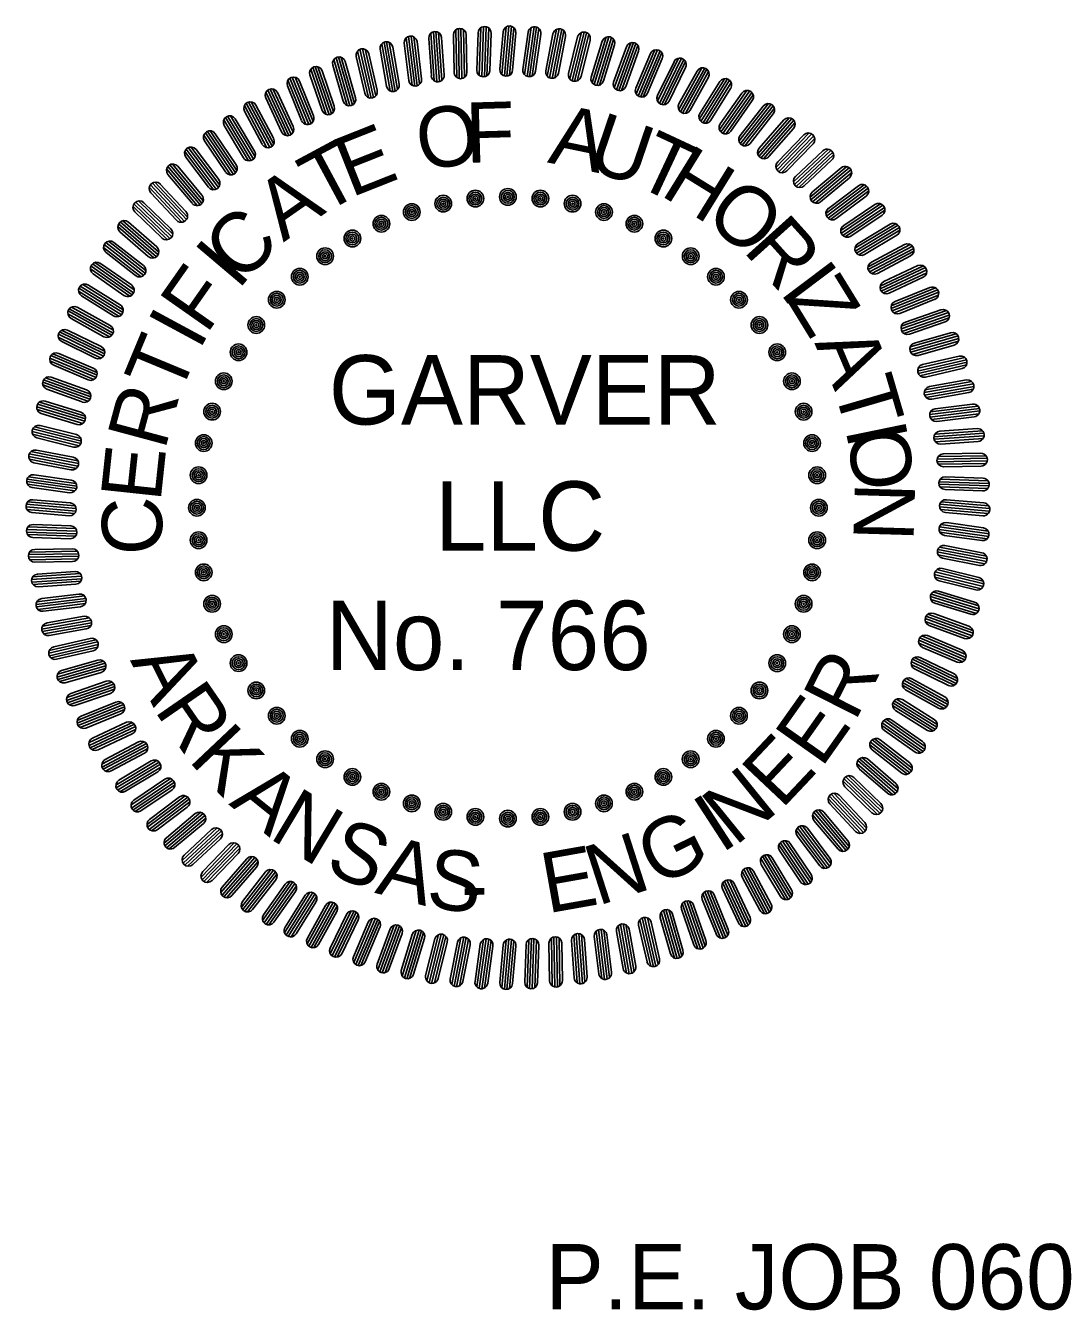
# Model space of a CAD drawing. Extents: x 1373884 to 1377798, y 1168424 to 1170626.
# Drawn here: x 1377288.9 to 1377543.4, y 1168462.5 to 1168777.3 of the extents above; entities that cross this region are included whole.
import ezdxf

# ---------------------------------------------------------------- set-up
doc = ezdxf.new("R2010")
doc.units = 0
doc.layers.add('2', color=7, linetype='Continuous')
doc.layers.add('G-ANNO-TEXT', color=7, linetype='Continuous')

# ---------------------------------------------------------------- blocks, each defined once
blk = doc.blocks.new('SEALDO')
at = {"layer": 'G-ANNO-TEXT'}
for radius in [0.0396, 0.0305, 0.0213, 0.0122, 0.00305]:
    blk.add_circle((1.403, -0.4559), radius, dxfattribs=at)
blk = doc.blocks.new('SEALRI')
at = {"layer": 'G-ANNO-TEXT'}
for p, q in [((-0.0226, 2.2583), (-0.0381, 2.0809)), ((-0.0083, 2.2815), (-0.0281, 2.0555)), ((0.0043, 2.2859), (-0.0164, 2.049)), ((0.0164, 2.2848), (-0.0043, 2.0479)), ((0.0281, 2.2783), (0.0083, 2.0523)), ((0.0226, 2.0756), (0.0381, 2.253))]:
    blk.add_line(p, q, dxfattribs=at)
for centre, start, end in [((0.0078, 2.2556), 355, 175), ((-0.0078, 2.0782), 175, 355)]:
    blk.add_arc(centre, 0.0305, start, end, dxfattribs=at)

msp = doc.modelspace()

# ---------------------------------------------------------------- block references
at = {"layer": 'G-ANNO-TEXT'}
for name, xscale, yscale, rotation in [('SEALRI', 51.64309671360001, 51.643096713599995, 3.0000000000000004), ('SEALRI', 51.64309671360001, 51.6430967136, -2.999999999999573), ('SEALRI', 51.643096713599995, 51.64309671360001, 15.000000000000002), ('SEALRI', 51.643096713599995, 51.643096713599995, 12), ('SEALRI', 51.64309671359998, 51.64309671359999, 9.000000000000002), ('SEALRI', 51.6430967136, 51.643096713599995, 6.000000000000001), ('SEALRI', 51.6430967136, 51.643096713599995, -5.99999999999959), ('SEALRI', 51.643096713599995, 51.64309671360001, -8.999999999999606), ('SEALRI', 51.64309671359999, 51.64309671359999, -11.999999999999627), ('SEALRI', 51.6430967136, 51.64309671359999, -14.99999999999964), ('SEALRI', 51.64309671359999, 51.64309671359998, 18.000000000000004), ('SEALRI', 51.643096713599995, 51.643096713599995, -17.999999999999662), ('SEALRI', 51.6430967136, 51.643096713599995, 23.99999999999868), ('SEALRI', 51.6430967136, 51.643096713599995, 20.99999999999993), ('SEALRI', 51.64309671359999, 51.64309671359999, -20.999999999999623), ('SEALRI', 51.643096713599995, 51.6430967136, -23.999999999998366), ('SEALRI', 51.6430967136, 51.643096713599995, 26.999999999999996), ('SEALRI', 51.643096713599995, 51.643096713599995, -26.99999999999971), ('SEALRI', 51.6430967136, 51.64309671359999, 30.000000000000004), ('SEALRI', 51.64309671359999, 51.6430967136, -29.999999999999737), ('SEALRI', 51.643096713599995, 51.64309671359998, 33), ('SEALRI', 51.6430967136, 51.6430967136, -32.999999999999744), ('SEALRI', 51.643096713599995, 51.64309671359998, 36), ('SEALRI', 51.643096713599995, 51.643096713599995, -35.999999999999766), ('SEALRI', 51.6430967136, 51.6430967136, 38.999999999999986), ('SEALRI', 51.64309671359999, 51.64309671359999, -38.99999999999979), ('SEALRI', 51.64309671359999, 51.64309671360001, 41.99999999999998), ('SEALRI', 51.6430967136, 51.643096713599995, -41.99999999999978), ('SEALRI', 51.643096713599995, 51.64309671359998, 44.999999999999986), ('SEALRI', 51.6430967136, 51.6430967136, -44.99999999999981), ('SEALRI', 51.643096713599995, 51.6430967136, 48), ('SEALRI', 51.6430967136, 51.643096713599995, -47.99999999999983), ('SEALDO', 51.64309671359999, 51.64309671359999, 119.99999999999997), ('SEALDO', 51.64309671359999, 51.64309671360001, 113.99999999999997), ('SEALDO', 51.643096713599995, 51.64309671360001, 107.99999999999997), ('SEALDO', 51.64309671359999, 51.64309671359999, 101.99999999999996), ('SEALDO', 51.6430967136, 51.643096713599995, 95.99999999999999), ('SEALRI', 51.643096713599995, 51.6430967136, 50.99999999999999), ('SEALDO', 51.6430967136, 51.6430967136, 125.99999999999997), ('SEALDO', 51.643096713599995, 51.643096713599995, 90), ('SEALRI', 51.643096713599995, 51.6430967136, -50.99999999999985), ('SEALRI', 51.643096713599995, 51.64309671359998, 54.00000000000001), ('SEALDO', 51.6430967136, 51.643096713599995, 131.99999999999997), ('SEALDO', 51.6430967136, 51.6430967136, 83.99999999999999), ('SEALRI', 51.6430967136, 51.643096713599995, -53.99999999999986), ('SEALDO', 51.643096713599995, 51.643096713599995, 138), ('SEALDO', 51.643096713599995, 51.6430967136, 77.99999999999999), ('SEALRI', 51.643096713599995, 51.6430967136, 56.999999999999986), ('SEALDO', 51.64309671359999, 51.64309671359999, 144), ('SEALDO', 51.64309671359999, 51.64309671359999, 72), ('SEALRI', 51.6430967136, 51.6430967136, -56.999999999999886), ('SEALRI', 51.64309671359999, 51.6430967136, 59.999999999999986), ('SEALDO', 51.643096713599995, 51.6430967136, 150), ('SEALDO', 51.6430967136, 51.6430967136, 66.00000000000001), ('SEALRI', 51.64309671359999, 51.64309671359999, -59.99999999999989), ('SEALRI', 51.64309671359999, 51.64309671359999, 63), ('SEALRI', 51.643096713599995, 51.6430967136, -62.99999999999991), ('SEALDO', 51.643096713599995, 51.6430967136, 156.00000000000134), ('SEALDO', 51.643096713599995, 51.6430967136, 60.00000000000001), ('SEALRI', 51.6430967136, 51.6430967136, 65.99999999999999), ('SEALRI', 51.6430967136, 51.64309671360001, -65.99999999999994), ('SEALDO', 51.64309671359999, 51.6430967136, 162.00000000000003), ('SEALDO', 51.643096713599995, 51.64309671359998, 54.00000000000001), ('SEALRI', 51.64309671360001, 51.6430967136, 68.99999999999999), ('SEALRI', 51.643096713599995, 51.6430967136, -68.99999999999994), ('SEALDO', 51.64309671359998, 51.643096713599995, 168.00000000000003), ('SEALDO', 51.6430967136, 51.643096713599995, 48.00000000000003), ('SEALRI', 51.64309671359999, 51.64309671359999, 72), ('SEALRI', 51.643096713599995, 51.6430967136, -71.99999999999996), ('SEALDO', 51.6430967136, 51.643096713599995, 174.00000000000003), ('SEALDO', 51.643096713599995, 51.6430967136, 42.00000000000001), ('SEALRI', 51.643096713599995, 51.6430967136, 75.00000000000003), ('SEALRI', 51.6430967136, 51.643096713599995, -74.99999999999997), ('SEALRI', 51.643096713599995, 51.643096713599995, 78.00000000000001), ('SEALDO', 51.643096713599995, 51.64309671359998, 36), ('SEALRI', 51.643096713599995, 51.643096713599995, -78), ('SEALDO', 51.643096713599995, 51.643096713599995, -179.99999999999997), ('SEALRI', 51.643096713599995, 51.64309671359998, 81), ('SEALRI', 51.64309671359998, 51.64309671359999, -81.00000000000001), ('SEALDO', 51.64309671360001, 51.643096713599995, -173.99999999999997), ('SEALDO', 51.643096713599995, 51.6430967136, 29.999999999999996), ('SEALRI', 51.6430967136, 51.643096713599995, 84.00000000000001), ('SEALRI', 51.6430967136, 51.643096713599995, -84.00000000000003), ('SEALDO', 51.6430967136, 51.643096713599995, 23.99999999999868), ('SEALRI', 51.6430967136, 51.6430967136, 87.00000000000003), ('SEALDO', 51.64309671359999, 51.6430967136, -167.99999999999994), ('SEALRI', 51.6430967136, 51.6430967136, -87.00000000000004), ('SEALRI', 51.643096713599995, 51.643096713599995, 90.00000000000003), ('SEALDO', 51.64309671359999, 51.64309671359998, -161.9999999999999), ('SEALDO', 51.64309671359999, 51.64309671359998, 18.000000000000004), ('SEALRI', 51.643096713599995, 51.643096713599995, -90.00000000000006), ('SEALRI', 51.64309671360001, 51.643096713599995, 93), ('SEALRI', 51.64309671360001, 51.6430967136, -93.00000000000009), ('SEALDO', 51.6430967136, 51.6430967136, -156.00000000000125), ('SEALDO', 51.643096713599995, 51.643096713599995, 12), ('SEALRI', 51.6430967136, 51.6430967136, 96.00000000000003), ('SEALRI', 51.643096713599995, 51.643096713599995, -96.0000000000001), ('SEALDO', 51.6430967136, 51.643096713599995, -149.99999999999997), ('SEALDO', 51.6430967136, 51.643096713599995, 6.000000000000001), ('SEALRI', 51.643096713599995, 51.643096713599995, 99.00000000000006), ('SEALRI', 51.643096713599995, 51.643096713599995, -99.00000000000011), ('SEALRI', 51.64309671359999, 51.64309671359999, 102.00000000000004), ('SEALDO', 51.64309671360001, 51.6430967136, -143.99999999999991), ('SEALRI', 51.643096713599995, 51.6430967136, -102.00000000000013), ('SEALRI', 51.6430967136, 51.643096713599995, 105.00000000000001), ('SEALRI', 51.6430967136, 51.643096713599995, -105.00000000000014), ('SEALDO', 51.6430967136, 51.6430967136, -137.9999999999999), ('SEALDO', 51.6430967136, 51.6430967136, -6.000000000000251), ('SEALRI', 51.643096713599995, 51.6430967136, 108.00000000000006), ('SEALRI', 51.6430967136, 51.643096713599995, -108.00000000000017), ('SEALRI', 51.64309671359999, 51.6430967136, 111.00000000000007), ('SEALDO', 51.643096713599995, 51.643096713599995, -131.99999999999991), ('SEALDO', 51.64309671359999, 51.64309671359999, -12.000000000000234), ('SEALRI', 51.643096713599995, 51.643096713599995, -111.00000000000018), ('SEALRI', 51.6430967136, 51.643096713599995, 114.00000000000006), ('SEALDO', 51.6430967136, 51.643096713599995, -125.9999999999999), ('SEALDO', 51.64309671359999, 51.64309671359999, -18.00000000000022), ('SEALRI', 51.6430967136, 51.643096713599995, -114.0000000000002), ('SEALRI', 51.64309671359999, 51.64309671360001, 117.00000000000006), ('SEALDO', 51.64309671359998, 51.643096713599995, -119.99999999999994), ('SEALDO', 51.643096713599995, 51.64309671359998, -23.999999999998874), ('SEALRI', 51.64309671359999, 51.643096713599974, -117.00000000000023), ('SEALRI', 51.64309671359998, 51.643096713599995, 120.00000000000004), ('SEALRI', 51.643096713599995, 51.6430967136, -120.00000000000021), ('SEALDO', 51.643096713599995, 51.64309671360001, -113.99999999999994), ('SEALDO', 51.64309671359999, 51.64309671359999, -30.00000000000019), ('SEALRI', 51.64309671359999, 51.6430967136, 123.00000000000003), ('SEALRI', 51.643096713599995, 51.6430967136, -123.00000000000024), ('SEALRI', 51.643096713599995, 51.6430967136, 126.00000000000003), ('SEALDO', 51.643096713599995, 51.6430967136, -107.99999999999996), ('SEALDO', 51.643096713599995, 51.643096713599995, -36.00000000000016), ('SEALRI', 51.643096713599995, 51.643096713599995, -126.00000000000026), ('SEALDO', 51.643096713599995, 51.64309671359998, -101.99999999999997), ('SEALDO', 51.643096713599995, 51.643096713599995, -42.00000000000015), ('SEALRI', 51.643096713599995, 51.6430967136, 129.00000000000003), ('SEALDO', 51.6430967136, 51.643096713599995, -96), ('SEALDO', 51.6430967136, 51.64309671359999, -48.00000000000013), ('SEALRI', 51.64309671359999, 51.64309671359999, -129.00000000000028), ('SEALRI', 51.643096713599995, 51.643096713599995, 132), ('SEALDO', 51.643096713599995, 51.643096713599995, -90.00000000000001), ('SEALDO', 51.643096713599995, 51.64309671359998, -54.00000000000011), ('SEALRI', 51.64309671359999, 51.64309671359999, -132.00000000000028), ('SEALRI', 51.64309671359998, 51.64309671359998, 135), ('SEALDO', 51.6430967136, 51.643096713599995, -84.00000000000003), ('SEALDO', 51.64309671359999, 51.64309671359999, -78.00000000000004), ('SEALDO', 51.643096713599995, 51.643096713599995, -72.00000000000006), ('SEALDO', 51.643096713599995, 51.643096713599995, -66.00000000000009), ('SEALDO', 51.643096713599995, 51.6430967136, -60.0000000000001), ('SEALRI', 51.643096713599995, 51.643096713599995, -135.00000000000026), ('SEALRI', 51.643096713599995, 51.643096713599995, 138), ('SEALRI', 51.643096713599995, 51.64309671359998, -138.00000000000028), ('SEALRI', 51.643096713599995, 51.643096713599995, 140.99999999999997), ('SEALRI', 51.64309671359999, 51.64309671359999, -141.0000000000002), ('SEALRI', 51.64309671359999, 51.64309671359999, 144), ('SEALRI', 51.643096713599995, 51.643096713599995, -144.00000000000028), ('SEALRI', 51.6430967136, 51.643096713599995, 146.99999999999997), ('SEALRI', 51.6430967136, 51.6430967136, -147.00000000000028), ('SEALRI', 51.643096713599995, 51.6430967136, 149.99999999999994), ('SEALRI', 51.6430967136, 51.643096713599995, -150.00000000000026), ('SEALRI', 51.6430967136, 51.643096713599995, 152.99999999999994), ('SEALRI', 51.6430967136, 51.64309671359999, 156.00000000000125), ('SEALRI', 51.6430967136, 51.6430967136, -156.00000000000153), ('SEALRI', 51.64309671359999, 51.6430967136, -153.00000000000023), ('SEALRI', 51.643096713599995, 51.6430967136, 159), ('SEALRI', 51.643096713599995, 51.6430967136, -159.00000000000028), ('SEALRI', 51.64309671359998, 51.64309671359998, 161.99999999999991), ('SEALRI', 51.64309671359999, 51.64309671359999, 164.99999999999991), ('SEALRI', 51.643096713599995, 51.64309671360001, -165.0000000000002), ('SEALRI', 51.64309671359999, 51.64309671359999, -162.00000000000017), ('SEALRI', 51.643096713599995, 51.64309671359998, 167.99999999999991), ('SEALRI', 51.643096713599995, 51.643096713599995, 170.9999999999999), ('SEALRI', 51.643096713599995, 51.6430967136, 173.9999999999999), ('SEALRI', 51.64309671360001, 51.6430967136, 176.9999999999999), ('SEALRI', 51.643096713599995, 51.643096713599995, 179.99999999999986), ('SEALRI', 51.64309671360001, 51.6430967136, -177.00000000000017), ('SEALRI', 51.643096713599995, 51.643096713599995, -174.00000000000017), ('SEALRI', 51.643096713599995, 51.6430967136, -171.00000000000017), ('SEALRI', 51.643096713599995, 51.6430967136, -168.0000000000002)]:
    msp.add_blockref(name, (1377407.06, 1168659.14), dxfattribs=dict(at, xscale=xscale, yscale=yscale, rotation=rotation))
at = {"layer": 'G-ANNO-TEXT', "xscale": 51.643096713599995, "yscale": 51.643096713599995}
for name in ['SEALRI', 'SEALDO']:
    msp.add_blockref(name, (1377407.06, 1168659.14), dxfattribs=at)

# ---------------------------------------------------------------- texts
at = {"layer": '2'}
msp.add_text('P.E. JOB 060395', height=16, dxfattribs=at).set_placement((1377416.28, 1168462.68))
at = {"layer": 'G-ANNO-TEXT'}
for s, rotation, p in [('O', 8.2771, (1377385.68, 1168741.74)), ('F', 1.6104, (1377396.86, 1168743.65)), ('A', 348.2771, (1377416.58, 1168743.78)), ('U', 341.2772, (1377425.82, 1168742.3)), ('E', 21.6104, (1377368.59, 1168735.08)), ('T', 334.9438, (1377437.42, 1168738.56)), ('T', 28.2771, (1377361.46, 1168730.91)), ('H', 328.2771, (1377444.06, 1168735.94)), ('A', 34.9438, (1377352.07, 1168724.12)), ('O', 319.7874, (1377454.73, 1168729.88)), ('C', 44.3881, (1377341.61, 1168713.72)), ('R', 311.9933, (1377464.41, 1168722.15)), ('I', 49.7408, (1377340.86, 1168712.21)), ('F', 54.9438, (1377333.17, 1168701.4)), ('I', 307.0081, (1377473.41, 1168712.03)), ('Z', 301.6104, (1377475.15, 1168710.26)), ('I', 61.6104, (1377331.41, 1168697.42)), ('T', 67.4314, (1377326.46, 1168685.98)), ('A', 292.9752, (1377482.11, 1168699.54)), ('T', 286.3085, (1377486.73, 1168688.85)), ('R', 74.9438, (1377323, 1168672.98)), ('I', 281.6104, (1377489.69, 1168678.47)), ('O', 276.4823, (1377490.25, 1168677.94)), ('E', 83.8985, (1377321.94, 1168660.36)), ('N', 268.2771, (1377492.1, 1168665.49)), ('C', 91.8842, (1377322.6, 1168647.77)), ('A', 296.5747, (1377314.41, 1168621.76)), ('R', 63.0959, (1377492.07, 1168606.44)), ('R', 304.6183, (1377320.23, 1168609.61)), ('E', 54.7309, (1377483.86, 1168595.12)), ('K', 313.3805, (1377328.52, 1168597.26)), ('E', 46.6807, (1377474.09, 1168585.04)), ('A', 321.2584, (1377338.5, 1168586.47)), ('N', 38.9821, (1377462.68, 1168576.02)), ('N', 329.1099, (1377348.2, 1168578.31)), ('I', 32.979, (1377459.27, 1168574.27)), ('S', 337.6294, (1377361.82, 1168570.01)), ('G', 26.4132, (1377443.6, 1168566.04)), ('N', 17.8686, (1377429.06, 1168561.53)), ('A', 345.4073, (1377374.24, 1168564.8)), ('S', 352.8046, (1377386.76, 1168561.28)), ('E', 10.0695, (1377416.71, 1168559.7)), ('-', 0.8385, (1377395.67, 1168559.35))]:
    msp.add_text(s, height=14.76, rotation=rotation, dxfattribs=at).set_placement(p)
for s, p in [('GARVER', (1377363.19, 1168679.53)), ('LLC', (1377389.18, 1168648.61)), ('No. 766', (1377362.46, 1168619.36))]:
    msp.add_text(s, height=17, dxfattribs=at).set_placement(p)

doc.saveas('drawing.dxf')
